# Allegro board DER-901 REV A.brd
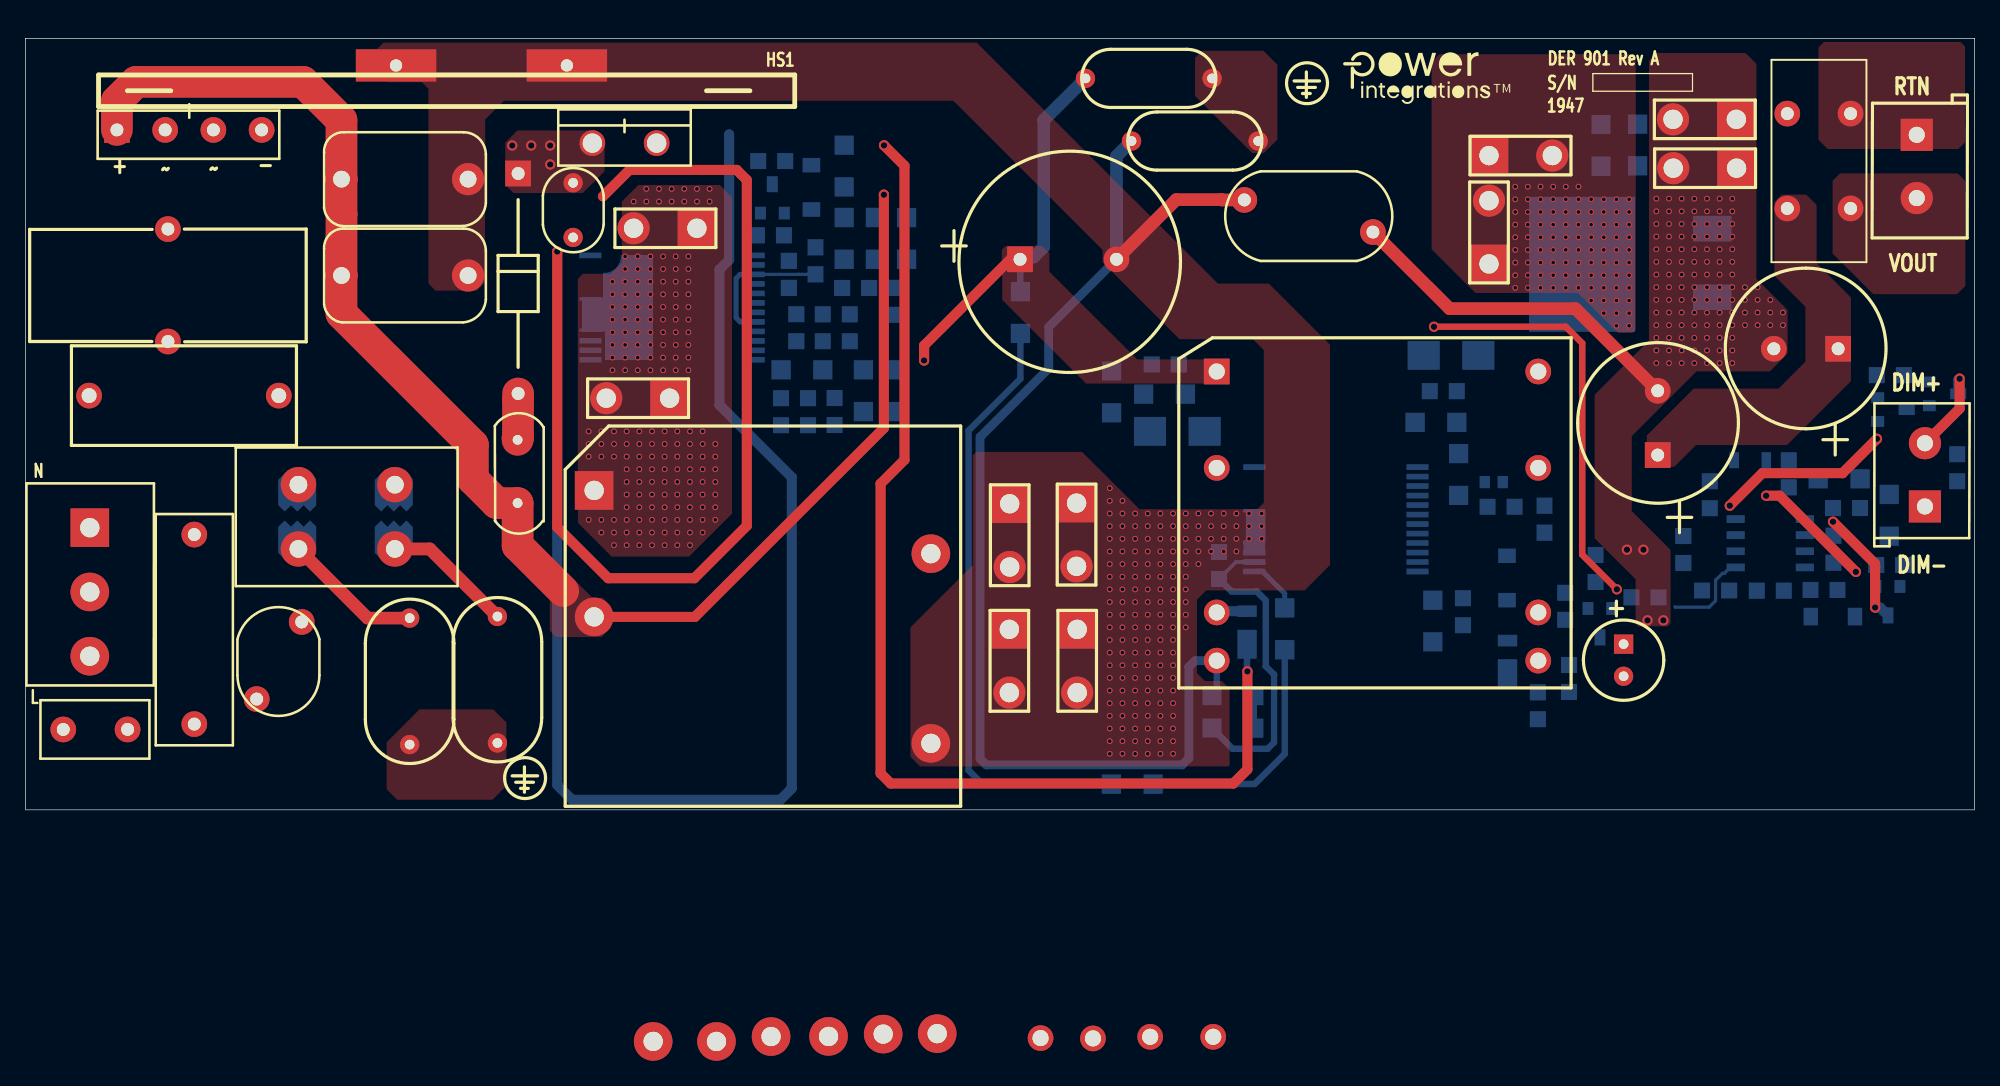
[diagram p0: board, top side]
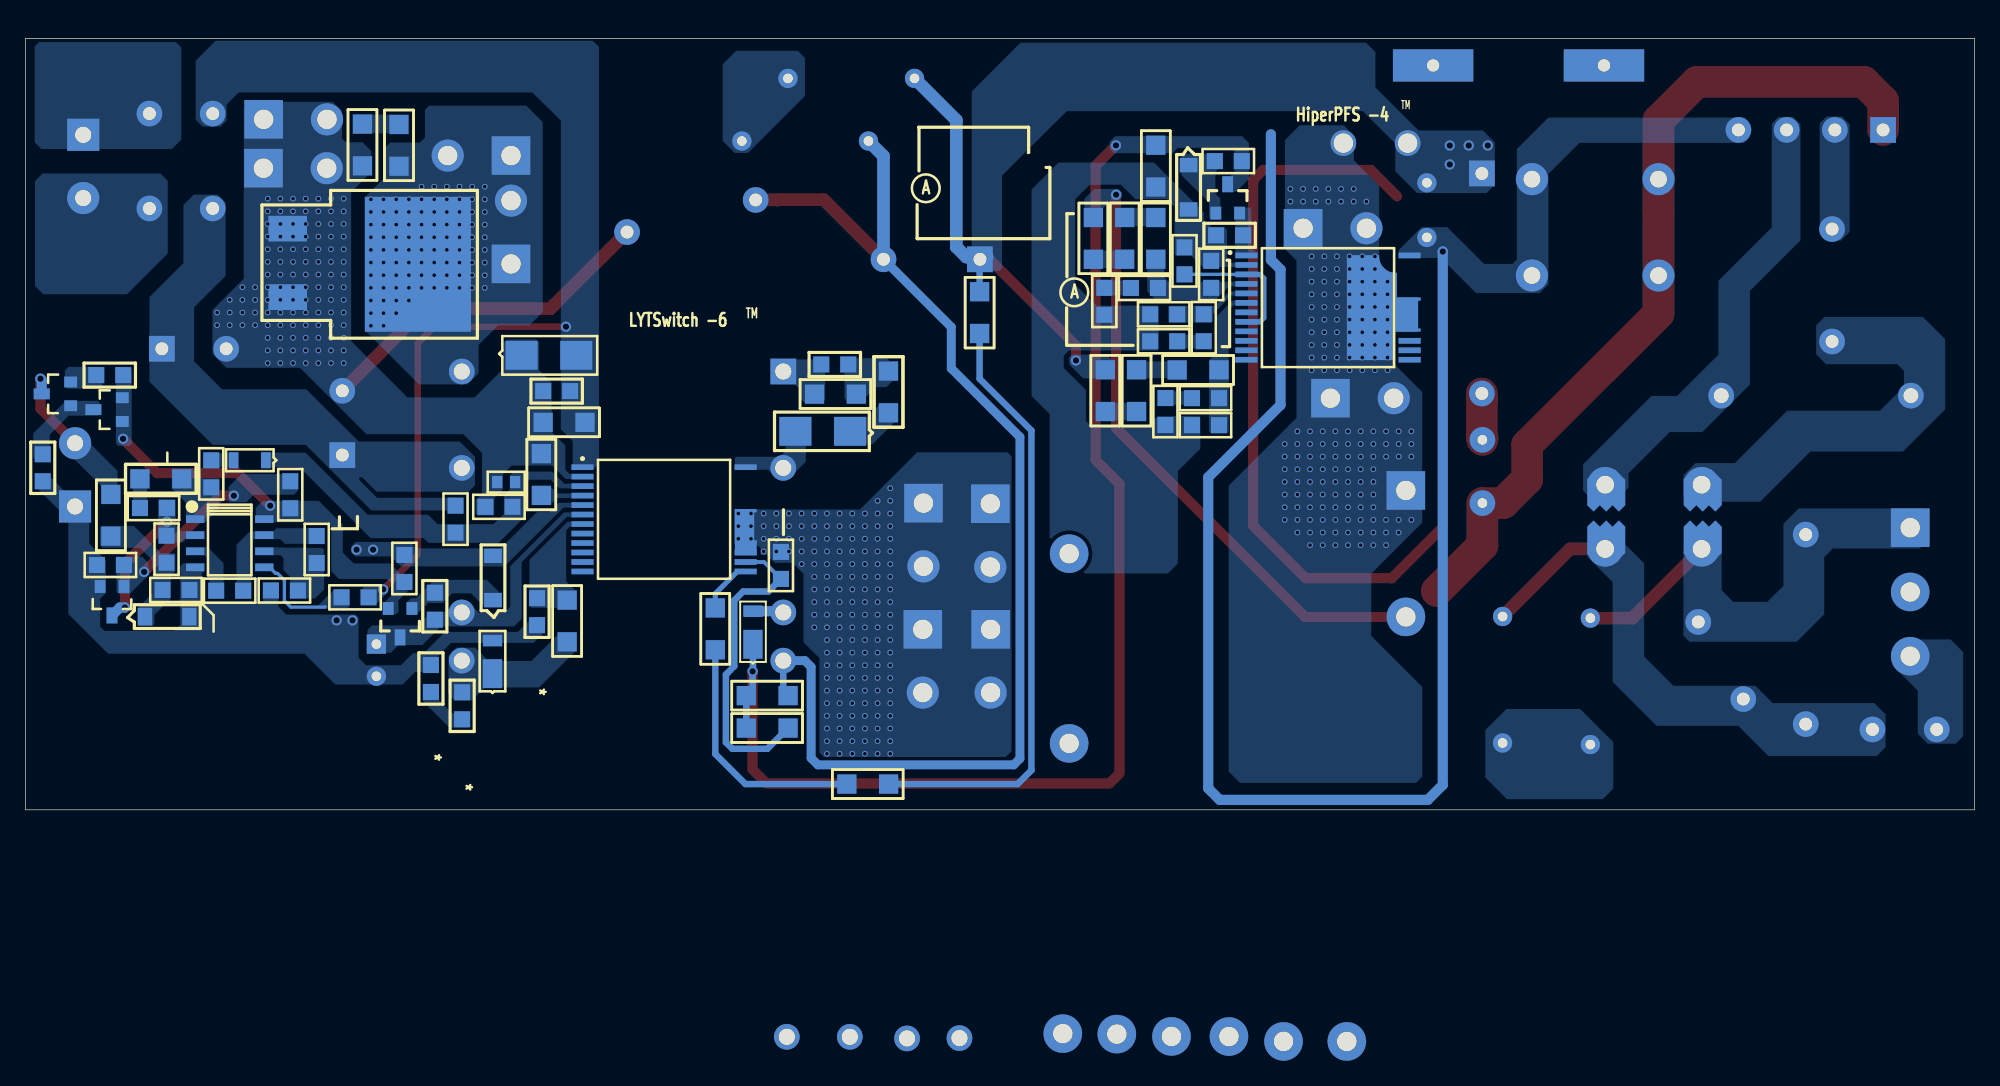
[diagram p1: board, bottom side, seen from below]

Outline 154 x 61 mm; copper layers: TOP, BOTTOM. Coordinates in mm from the lower left corner of the outline.
Outline path: 0,61 0,0 154,0 154,61 0,61

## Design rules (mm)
constraint set DEFAULT: min track width 0.508

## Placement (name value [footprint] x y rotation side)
BR1  UD4KB100-BP  [PIDAXBRIDGED3K]  7.24 53.76 0 top
C1  330 nF  [PI_NP_CAPRAD512X299LS394D040]  24.98 49.87 0 top
C2  330 nF  [PI_NP_CAPRAD512X299LS394D040]  24.98 42.25 0 top
C3  150 nF  [PINPXCAPRAD720X240590040]  13.35 6.78 90 top
C4  330 nF  [PINPXCAPRAD710X315590046]  20.02 32.75 180 top
C7  680 uF  [PIPOLCAPCLYD500LS200040]  128.96 28.05 90 top
C8  680 uF  [PIPOLCAPCLYD500LS200040]  143.21 36.45 180 top
C9  1 nF  [PISMC0805]  88.99 35.22 0 bottom
C10  47 pF  [PISMC1206]  127.37 54.22 270 bottom
C12  3.3 nF  [PINPYCAPRAD540X290LS400040]  96.3 48.22 0 top
C13  68 uF  [PIPOLCAPCLYD710LS300040]  78.58 43.53 0 top
C14  10 nF  [PI_NP_CAP250X200LS170D030]  43.28 49.58 270 top
C15  330 pF  [PISMC0603]  116.72 25.91 180 bottom
C16  2.2 uF  [PISMC1206]  113.23 28.16 270 bottom
C17  1 uF  [PISMC0805]  62.42 42.34 90 bottom
C18  1 uF  [PISMC0805]  57.8 45.43 0 bottom
C19  470 pF  [PISMC0805]  59.7 30.42 0 bottom
C20  10 uF  [PISMC1206]  64.69 52.55 270 bottom
C21  470 pF  [PISMC0805]  60.32 41.27 90 bottom
C22  100 nF  [PISMC0805]  63 39.18 0 bottom
C23  1 uF  [PISMC0805]  63 37.05 0 bottom
C25  1 uF  [PISMC0805]  133.07 25.98 270 bottom
C26  10 uF  [PISMC1206]  97.04 9.03 180 bottom
C27  4.7 uF  [PISMC0805]  94.3 18.26 90 bottom
C28  470 nF  [PISMC1206]  144.94 26.17 180 bottom
C29  3.3 uF  [PISMC0805]  141.03 17.38 0 bottom
C31  47 uF  [PIPOLCAPCYLD250LS100030]  126.26 13.1 270 top
C32  100 nF  [PISMC0805]  124.05 18.02 90 bottom
C33  2200 pF  [PINPCAPRAD9P0D10P0LS030]  37.3 15.29 270 top
C34  2200 pF  [PINPCAPRAD9P0D10P0LS030]  30.36 15.16 270 top
C35  2200 pF  [PINPCAPRAD9P0D10P0LS030]  83.75 57.83 0 top
C36  2200 pF  [PINPCAPRAD9P0D10P0LS030]  97.39 52.88 180 top
C37  22 pF  [PISMC0805]  121.95 11.45 270 bottom
C38  100 pF  [PISMC0805]  113.57 14.6 90 bottom
D2  1N4006  [PIDV200X110X040DO41]  38.93 48.71 270 top
D3  S1K-E3/61T  [PISMDO214AC12]  88.85 29.93 0 bottom
D4  STTH2003CG-TR  [PISMDD2PAK]  133.27 45.96 270 bottom
D5  LQA03TC600  [PIDVT0220ACREVA]  49.88 52.72 180 top
D7  DFLR1400-7  [PISMDDFLR120012]  96.51 13.06 270 bottom
D9  B340A-13-F  [PISMDO214AC12]  114.79 35.94 180 bottom
D11  DFLU1200-7  [PISMDDFLR120012]  117.09 10.74 270 bottom
D13  BAS21HT1G  [PISMSOD323]  135 27.64 0 bottom
F1  3.15 A  [PI_RST_MICROFUSE]  3 6.36 0 top
HS1  HEATSINK, SHTM, DER801, PI CUST, AL 3003  [PI_HS_2P_DER801]  60.78 58.11 90 top
J1  TERMINAL BLOCK  [PI_TERM_BLOCK_3PIN]  5.09 22.31 180 top
J2  TERMINAL BLOCK  [PI_TERM_BLOCK_2PIN_LS200]  149.42 53.37 180 top
J4  TERMINAL BLOCK  [PI_TERM_BLOCK_2PIN_LS200]  150.07 23.99 0 top
J6  CON2  [PI_CONN_QC_TAB_2PIN_LS200]  135.17 54.59 90 top
J7  CON2  [PI_CONN_QC_TAB_2PIN_LS200]  135.19 50.73 90 top
J8  CON2  [PI_CONN_QC_TAB_2PIN_LS200]  115.63 51.73 270 top
J9  CON2  [PI_CONN_QC_TAB_2PIN_LS200]  115.63 43.16 0 top
J10  CON2  [PI_CONN_QC_TAB_2PIN_LS200]  77.74 14.27 180 top
J11  CON2  [PI_CONN_QC_TAB_2PIN_LS200]  77.77 24.2 180 top
J12  CON2  [PI_CONN_QC_TAB_2PIN_LS200]  83.1 14.27 180 top
J13  CON2  [PI_CONN_QC_TAB_2PIN_LS200]  83.05 24.25 180 top
J14  CON2  [PI_CONN_QC_TAB_2PIN_LS200]  50.9 32.55 90 top
J15  CON2  [PI_CONN_QC_TAB_2PIN_LS200]  53.06 45.98 90 top
L1  20mH  [PI_IND_4P_690X512LS300X200D055]  21.57 20.63 90 top
L2  2120-V-RC  [PI_TOROID_2P_350X860_LS330_D038]  11.27 37.03 90 top
L3  1.8 mH  [PI_COIL_16X8_LS8X7P5]  144.2 47.55 90 top
NOREF  -  []  0 0 0 top
NOREF#2  -  []  154 0 90 top
NOREF#3  -  []  104.12 60.37 0 top
Q1  MMBTA06LT1G  [PISMSOT23123_1]  58.07 47.18 180 bottom
Q3  MMBT3906  [PISMSOT23123_1]  150.42 33.83 90 bottom
Q5  2N7002  [PISMSOT23123_1]  148.09 17.66 0 bottom
Q6  MMBTA06LT1G  [PISMSOT23123_1]  125.33 15.92 0 bottom
R4  510 k  [PISMR0805]  120.01 24.05 270 bottom
R5  240 k  [PISMR1206]  91.65 32.87 180 bottom
R6  20  [PISMR1206]  124.48 54.19 270 bottom
R7  15.4 k  [PISMR0805]  115.52 23.96 0 bottom
R8  3.74 M  [PISMR1206]  68.68 34.79 270 bottom
R9  6.2 M  [PISMR1206]  66.21 31.49 90 bottom
R10  6.2 M  [PISMR1206]  69.62 46.83 270 bottom
R11  6.2 M  [PISMR1206]  67.15 43.53 90 bottom
R12  6.2 M  [PISMR1206]  59.7 34.78 0 bottom
R13  3.74 M  [PISMR1206]  64.69 46.83 270 bottom
R14  18.2 k  [PISMR0805]  146.26 34.37 0 bottom
R15  30.1 k  [PISMR0805]  60.91 39.19 270 bottom
R17  10 k  [PISMR0805]  64.53 41.26 0 bottom
R18  143 k  [PISMR0805]  68.76 41.27 270 bottom
R19  10 k  [PISMR0805]  59.7 32.55 0 bottom
R20  143 k  [PISMR0805]  63.93 32.56 270 bottom
R21  15.0 k  [PISMR1206]  97.04 6.47 180 bottom
R22  200 k  [PISMR0805]  139.31 27.63 270 bottom
R23  20.0 k  [PISMR1206]  147.24 21.64 90 bottom
R24  0.02  [PISMR0805]  113.09 33.11 180 bottom
R27  10 k  [PISMR0805]  152.62 28.11 270 bottom
R29  10 k  [PISMR0805]  146.21 19.36 0 bottom
R30  47  [PISMR1206]  111.2 13.28 90 bottom
R31  0.027  [PISMR1206]  113.09 30.64 180 bottom
R32  0.0  [PISMR0805]  142.81 23.86 0 bottom
R34  249 k  [PISMR0805]  130.98 21.65 270 bottom
R37  1.00 k  [PISMR0805]  129.02 16.8 180 bottom
R38  1.00 k  [PISMR0805]  132.46 17.34 0 bottom
R39  1.00 k  [PISMR0805]  138.92 17.33 180 bottom
R41  1.00 k  [PISMR0805]  142.84 21.68 270 bottom
R45  1.33 M  [PISMR1206]  78.61 40.97 270 bottom
R46  1.33 M  [PISMR1206]  85.8 2.04 0 bottom
R47  1.33 M  [PISMR1206]  99.49 12.66 90 bottom
R50  100 k  [PISMR0805]  57.9 51.29 0 bottom
R53  30 k  [PISMR0805]  121.65 15.03 90 bottom
R54  20  [PISMR1206]  85.81 31.39 90 bottom
R55  22  [PISMR0805]  119.49 7.16 90 bottom
RT1  2.5  [PI_RAD150X300LS200D030]  38.89 24.25 90 top
RV1  300 Vac  [PIDISC350X225LS240X140040]  18.28 8.76 90 top
T3  PQ26/25  [PIBOBBINPQ262512P]  94.12 34.66 0 top
T4  EQ30  [PI_BOBBIN_EQ30_V_10P]  44.94 25.26 0 top
U2  PFS7628C  [PI_IC_INSOP24B]  51.09 39.71 180 bottom
U3  LM431BIM3/NOPB  [PISMSOT23123]  146.34 32.58 90 bottom
U4  LYT6070C  [PI_IC_INSOP_24D]  109.98 27.1 180 bottom
U5  TSX712IDT  [PISMSO8]  140.58 22.99 270 bottom
VR1  MMSZ4700T1G  [PI_SM_SOD-123_12]  62.1 50.97 270 bottom
VR2  MMSZ5242B-7-F  [PI_SM_SOD-123_12]  144.55 15.28 180 bottom
VR3  MMSZ4700T1G  [PI_SM_SOD-123_12]  117.05 16.58 90 bottom

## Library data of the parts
BR1 = DISCRETE BRIDGE_+~~-: alternate symbols: (pidaxbridgeD3K_horz)
C1 C2 = CAP NP: alternate symbols: (pi_np_caprad512x299ls394d040_h)
C3 C4 C9 C10 C14-C19 C21-C23 C25 C27-C29 C32-C38 = CAP NP
C7 C8 = CAP POL: alternate symbols: (pipolcapclyd500ls2000401000lh)
C12 = CAP NP: alternate symbols: (pinpycaprad540x290ls400040h)
C13 = CAP POL: alternate symbols: (pi_cap_cly_d710_ls300_040_1000h)
C20 C26 = CAP NP: alternate symbols: (pismc1206_1)
C31 = CAP POL: alternate symbols: (pipolcapcyld250ls100030h)
D2 = DIODE: alternate symbols: (pidax475x125040do41,pidv200x110x040do41wbead,pidax390x125040do41)
D3 D5 D7 D11 = DIODE
D4 = D_DUAL_CK_AKA
D9 = DIODE SCHOTTKY
D13 = DIODE: alternate symbols: (pismsod323_1)
F1 = FUSE: alternate symbols: (pirstmicrofusehoz)
HS1 = hs_2P_DER801
J1 = CON3
J2 J4 J6-J15 = CON2
L1 = INDUCTOR_4P_revD: alternate symbols: (pi_4p_700x400d055_horiz)
L2 = INDUCTOR: alternate symbols: (pi_2p_700x400d055_horiz)
L3 = TORRID 4P_14_23
Q1 Q6 = NPN_BEC
Q3 = PNP_BEC
Q5 = FET_N_GSD
R4-R15 R17-R24 R27 R29-R31 R34 R37-R39 R41 R45-R47 R50 R53-R55 = R
R32 = R: alternate symbols: (pismr0805_1)
RT1 = THERMISTOR: alternate symbols: (pirad400x300ls200040_h)
RV1 = VARISTOR
T3 = BPQ26/25_12P/GENERIC
T4 = BEQ30_10P/GENERIC
U2 = HIPERPFS-4-inSOP24B_0
U3 = TL431/SOT-23_CAR
U4 = LYT6
U5 = TSX712IDT
VR1-VR3 = DIODE_ZENER

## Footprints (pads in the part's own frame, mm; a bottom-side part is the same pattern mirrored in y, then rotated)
PI_BOBBIN_EQ30_V_10P
  rect 3.048x3.048 hole 1.524: 1(0,0)
  round 3.048 hole 1.524: 2(27.102,-42.949) 3(0,-10) 4(18.517,-43.17) 5(22.835,-42.987) 6(26.601,-20) 7(9.665,-43.566) 8(4.663,-43.566) 9(26.601,-5.001) 10(13.978,-43.18)
PI_COIL_16X8_LS8X7P5
  round 2.032 hole 1.016: 1(0,5) 2(7.5,5) 3(7.5,0) 4(0,0)
PI_CONN_QC_TAB_2PIN_LS200
  rect 3.048x3.048 hole 1.524: 1(0,0)
  round 2.54 hole 1.524: 2(0,5.001)
PI_HS_2P_DER801
  rect 2.54x6.35 hole 0.965: 1(0.75,18) 2(0.75,31.5)
PI_IC_INSOP24B
  rect 1.75x0.45 smd: 1(-6.445,4.125) 2(-6.445,3.375) 3(-6.445,2.625) 4(-6.445,1.875) 5(-6.445,1.125) 6(-6.445,0.375) 7(-6.445,-0.375) 8(-6.445,-1.125) 9(-6.445,-1.875) 10(-6.445,-2.625) 11(-6.445,-3.375) 12(-6.445,-4.125) 13(6.445,-4.125) 14(6.445,-3.375) 15(6.445,-2.625) 24(6.445,4.125)
  custom 0.438x0.438 smd: 16(6.445,-0.545)
PI_IC_INSOP_24D
  rect 1.75x0.45 smd: 1(0,0) 2(0,-0.75) 3(0,-1.5) 4(0,-2.25) 5(0,-3) 6(0,-3.75) 7(0,-4.5) 8(0,-5.25) 9(0,-6) 10(0,-6.75) 11(0,-7.5) 12(0,-8.25) 13(12.89,-8.25) 14(12.89,-7.5) 15(12.89,-6.75) 24(12.89,0)
  custom 0.438x0.438 smd: 16(12.89,-4.67)
PI_IND_4P_690X512LS300X200D055
  round 2.794 hole 1.397: 1(0,0) 2(5.08,0) 3(5.08,-7.62) 4(0,-7.62)
PI_NP_CAP250X200LS170D030
  round 1.524 hole 0.762: 1(0,0) 2(4.318,0)
PI_NP_CAPRAD512X299LS394D040
  round 2.54 hole 1.321: 1(0,0) 2(10,0)
PI_RAD150X300LS200D030
  round 2.032 hole 0.762: 1(0,0) 2(5,0)
PI_RST_MICROFUSE
  round 2.032 hole 1.016: 1(0,0) 2(5.08,0)
PI_SM_SOD-123_12
  rect 1.143x1.397 smd: 1(0,0) 2(3.505,0)
PI_TERM_BLOCK_2PIN_LS200
  rect 2.54x2.54 hole 1.27: 1(0,0)
  round 2.54 hole 1.27: 2(0,5.001)
PI_TERM_BLOCK_3PIN
  rect 3.048x3.048 hole 1.524: 1(0,0)
  round 3.048 hole 1.524: 2(0,5.08) 3(0,10.16)
PI_TOROID_2P_350X860_LS330_D038
  round 2.032 hole 1.016: 1(0,0) 2(8.89,0)
PIBOBBINPQ262512P
  rect 2.032x2.032 hole 1.27: 1(0,0)
  round 2.032 hole 1.27: 2(-13.919,-52.705) 3(0,-7.62) 4(-9.779,-52.73) 5(0,-19.05) 6(0,-22.86) 7(25.4,-22.86) 8(25.4,-19.05) 9(-5.258,-52.603) 10(25.4,-7.62) 11(-0.279,-52.603) 12(25.4,0)
PIDAXBRIDGED3K
  rect 2.032x2.032 hole 1.016: 1(0,0)
  round 2.032 hole 1.016: 2(3.81,0) 3(7.62,0) 4(11.43,0)
PIDISC350X225LS240X140040
  round 2.032 hole 1.016: 1(0,0) 2(6.096,-3.556)
PIDV200X110X040DO41
  rect 2.032x2.032 hole 1.016: 1(-1.6,0)
  round 2.032 hole 1.016: 2(15.795,0)
PIDVT0220ACREVA
  round 2.032 hole 1.524: 1(5.08,0) 2(0,0)
PINPCAPRAD9P0D10P0LS030
  round 1.524 hole 0.762: 1(0,0) 2(10,0)
PINPXCAPRAD710X315590046
  round 2.032 hole 1.168: 1(0,0) 2(14.986,0)
PINPXCAPRAD720X240590040
  round 2.032 hole 1.016: 1(0,0) 2(14.986,0)
PINPYCAPRAD540X290LS400040
  round 2.032 hole 1.016: 1(0,0) 2(10.16,-2.54)
PIPOLCAPCLYD500LS200040
  rect 2.032x2.032 hole 1.016: 1(0,0)
  round 2.032 hole 1.016: 2(5.08,0)
PIPOLCAPCLYD710LS300040
  rect 2.032x2.032 hole 1.016: 1(0,0)
  round 2.032 hole 1.016: 2(7.62,0)
PIPOLCAPCYLD250LS100030
  rect 1.524x1.524 hole 0.762: 1(0,0)
  round 1.524 hole 0.762: 2(2.54,0)
PISMC0603
  rect 0.813x0.965 smd: 1(0,0) 2(1.422,0)
PISMC0805
  rect 1.27x1.27 smd: 1(0,0) 2(2.134,0)
PISMC1206
  rect 1.524x1.524 smd: 1(0,0) 2(3.302,0)
PISMDD2PAK
  rect 2.032x3.048 smd: 1(0.005,0) 3(5.42,0)
  rect 10.668x8.382 smd: 2(2.825,10.287)
PISMDDFLR120012
  rect 2.286x1.524 smd: 1(-0.025,0)
  rect 0.914x1.524 smd: 2(-2.642,0)
PISMDO214AC12
  rect 2.54x2.286 smd: 1(0,0) 2(4.318,0)
PISMR0805
  rect 1.27x1.27 smd: 1(0,0) 2(2.134,0)
PISMR1206
  rect 1.524x1.524 smd: 1(0,0) 2(3.302,0)
PISMSO8
  rect 0.61x1.448 smd: 1(0,0) 2(1.27,0) 3(2.54,0) 4(3.81,0) 5(3.81,5.461) 6(2.54,5.461) 7(1.27,5.461) 8(0,5.461)
PISMSOD323
  rect 0.762x1.27 smd: 1(0,0) 2(2.54,0)
PISMSOT23123
  rect 0.864x1.016 smd: 1(-1.88,0) 3(0,0)
  rect 0.864x1.27 smd: 2(-0.94,2.286)
PISMSOT23123_1
  rect 0.864x1.016 smd: 1(-1.88,0) 2(0,0)
  rect 0.864x1.27 smd: 3(-0.94,2.286)

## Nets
GND_EARTH: C33.2 C34.2 C35.2 C36.1
15 VDC AUX: C20.1 C26.1 D7.1 Q1.3 R21.1 R50.1
DIM+: J4.2 Q3.3 R23.2
DIM-: C7.2 C8.2 C10.2 C12.2 C15.1 C16.1 C29.1 C31.2 C32.2 C37.1 C38.1 D4.1 D4.3 D9.1 D11.2 J4.1 J6.1 J6.2 J7.1 J7.2 Q5.2(S) R7.2 R24.1 R27.2 R29.2 R31.1 R38.2 U4.2 U4.5 U5.4 VR2.2 VR3.2
FB_PIN: C15.2 D13.1 R4.2 R7.1 U4.3
NC8: U4.8
NC9: U4.9
NC10: U4.10
NC11: U4.11
NC12: U4.12
NC15: U4.15
RS+: D9.2 L3.2 R24.2 R31.2 R37.2 U4.1
SB_A: D11.1 R30.1 R55.2 T3.7
SB_B: C31.1 Q6.3 R53.1 T3.8 U4.6
SOURCE: BR1.4 C1.2 C2.2 C12.1 C13.2 C14.2 C26.2 C27.2 C36.2 HS1.1 HS1.2 J10.1 J10.2 J11.1 J11.2 J12.1 J12.2 J13.1 J13.2 T3.6 T4.6 U2.24 U4.16
VRECT: BR1.1 C1.1 C2.1 R10.1 RT1.1 T4.3
N11474046: F1.1 J1.3
N11474062: C3.1 C33.1 F1.2 L1.4 RV1.1
N11474114: BR1.3(AC2) C4.1 L1.3
N11474138: BR1.2 L2.2
N11474236: C3.2 C34.1 J1.1 L1.1 RV1.2
N11474420: C4.2 L1.2 L2.1
N11475153: C9.2 C13.1 C14.1 C35.1 D2.1 D5.1 R5.1 R8.1 R45.1 T3.1
N11476179: D5.2 J14.1 J14.2 J15.1 J15.2 T4.1 U2.16
N11479125: C18.1 Q1.2(EMITTER) U2.1(VCC)
N11479237: C17.2 C18.2 C19.2 C20.2 C21.2 C22.2 C23.2 R18.2 R20.2 U2.2 U2.12 VR1.2
N11479555: C22.1 R15.1 U2.5
N11479611: C23.1 R15.2
N11480020: C21.1 R13.2 R17.1 U2.4
N11480864: R10.2 R11.1
N11480868: R11.2 R13.1
N11482311: R8.2 R9.1
N11482333: R9.2 R12.2
N11482355: C19.1 R12.1 R19.1 U2.6
N11498787: C7.1 C8.1 L3.1 R4.1 T3.10
N11498945: C9.1 R5.2 R54.2
N11499171: D4.2(CATHODE) J8.1 J8.2 J9.1 J9.2 R6.2 T3.12
N11499175: C10.1 R6.1
N11499225: D3.2 T3.3 U4.24
N11499609: C38.2 R30.2 U4.7
N11499655: C16.2 U4.4
N11499799: C27.1 R21.2 U4.14
N11939314: R19.2 R20.1
N11966145: D7.2 T3.5
N11977822: C17.1 U2.3 U2.8
N11995900: Q1.1 R50.2 VR1.1
N12000412: R17.2 R18.1
N12016680: R45.2 R46.1
N12017060: R46.2 R47.1
N12033400: C25.2 C32.1 Q6.2(EMITTER) R14.1 U3.1 U3.3(VREF) U5.8
N12033444: Q3.2(EMITTER) R14.2
N12033508: Q3.1 R27.1 U3.2
N12033698: R39.1 U5.3
N12033710: C29.2 R23.1 R41.2 VR2.1
N12033758: D13.2 R22.1
N12033766: C28.2 R22.2 U5.1
N12033774: Q5.3 R32.1 R41.1 U5.2
N12033856: C25.1 Q5.1 R29.1
N12033928: C28.1 R32.2
N12034132: R34.2 R38.1 U5.6
N12034136: R34.1 R39.2 U5.7(OUT)
N12052159: Q6.1 R53.2 VR3.1
N12053445: D3.1 R54.1
N12080403: R37.1 U5.5
N12174734: C37.2 R55.1
N12244813: D2.2 RT1.2
N12258356: R47.2 U4.13(VPIN)
N12288102: J2.2 L3.4
N12288115: J2.1 L3.3

Pads without a net: J1 2; T3 2 4 9 11; T4 2 4 5 7 8 9 10; U2 7 9 10 11 13 14 15

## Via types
v1: diameter 0.457, hole 0.305, TOP to BOTTOM, 534 vias
v2: diameter 0.813, hole 0.508, TOP to BOTTOM, 22 vias

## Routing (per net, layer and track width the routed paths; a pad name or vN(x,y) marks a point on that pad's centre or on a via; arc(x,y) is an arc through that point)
15 VDC AUX: length 95.5
  TOP w0.8: v2(96.55,10.95) 96.55,3.2 95.43,2.08 68.36,2.08 67.56,2.88 67.56,25.78 69.45,27.67 69.45,50.92 v2(67.84,52.54)
  BOTTOM w0.508: R21.1 97.04,7.74 C26.1 96.55,9.53 v2(96.55,10.95) 96.51,10.98 D7.1
DIM+: length 7.5
  TOP w0.8: J4.2 152.81,31.72 v2(152.81,34.09)
  BOTTOM w0.8: v2(152.81,34.09) 152.7,33.98 Q3.3
DIM-: length 27.7
  TOP w1: C12.2 112.52,39.62 122.47,39.62 C7.2
  vias: v1(128.85,48.32) v1(128.85,47.32) v1(128.85,46.32) v1(128.85,45.32) v1(128.85,44.32) v1(128.85,43.32) v1(128.85,42.32) v1(128.85,41.32) v1(128.85,40.32) v1(128.85,39.32) v1(128.85,38.32) v1(128.85,37.32) v1(128.85,36.32) v1(128.85,35.32) v1(129.85,48.32) v1(129.85,47.32) v1(129.85,46.32) v1(129.85,45.32) v1(129.85,44.32) v1(129.85,43.32) v1(129.85,42.32) v1(129.85,41.32) v1(129.85,40.32) v1(129.85,39.32) v1(129.85,38.32) v1(129.85,37.32) v1(129.85,36.32) v1(129.85,35.32) v1(130.85,48.32) v1(130.85,47.32) v1(130.85,46.32) v1(130.85,45.32) v1(130.85,44.32) v1(130.85,43.32) v1(130.85,42.32) v1(130.85,41.32) v1(130.85,40.32) v1(130.85,39.32) v1(130.85,38.32) v1(130.85,37.32) v1(130.85,36.32) v1(130.85,35.32) v1(131.85,48.32) v1(131.85,47.32) v1(131.85,46.32) v1(131.85,45.32) v1(131.85,44.32) v1(131.85,43.32) v1(131.85,42.32) v1(131.85,41.32) v1(131.85,40.32) v1(131.85,39.32) v1(131.85,38.32) v1(131.85,37.32) v1(131.85,36.32) v1(131.85,35.32) v1(132.85,48.32) v1(132.85,47.32) v1(132.85,46.32) v1(132.85,45.32) v1(132.85,44.32) v1(132.85,43.32) v1(132.85,42.32) v1(132.85,41.32) v1(132.85,40.32) v1(132.85,39.32) v1(132.85,38.32) v1(132.85,37.32) v1(132.85,36.32) v1(132.85,35.32) v1(133.85,48.32) v1(133.85,47.32) v1(133.85,46.32) v1(133.85,45.32) v1(133.85,44.32) v1(133.85,43.32) v1(133.85,42.32) v1(133.85,41.32) v1(133.85,40.32) v1(133.85,39.32) v1(133.85,38.32) v1(133.85,37.32) v1(133.85,36.32) v1(133.85,35.32) v1(134.85,48.32) v1(134.85,47.32) v1(134.85,46.32) v1(134.85,45.32) v1(134.85,44.32) v1(134.85,43.32) v1(134.85,42.32) v1(134.85,41.32) v1(134.85,40.32) v1(134.85,39.32) v1(134.85,38.32) v1(134.85,37.32) v1(134.85,36.32) v1(134.85,35.32) v1(135.85,41.32) v1(135.85,40.32) v1(135.85,39.32) v1(135.85,38.32) v1(136.85,41.32) v1(136.85,40.32) v1(136.85,39.32) v1(136.85,38.32) v1(137.85,40.32) v1(137.85,39.32) v1(137.85,38.32) v1(138.85,39.32) v1(138.85,38.32) v2(126.53,20.57) v2(127.83,20.57) v2(128.15,14.98) v2(129.41,14.98)
RS+: length 32.8
  TOP w0.508: v2(111.29,38.2) 121.7,38.2 123,36.9 123,20.17 v2(125.73,17.44)
SOURCE: length 291.3
  TOP w0.8: 45.63,48.5 47.73,50.6 56.2,50.6 57,49.8 57,22.46 52.85,18.31 46.05,18.31 42.02,22.34 v2(42.02,44.14)
  TOP w1: C12.1 94.53,48.22 94.51,48.25 90.92,48.25 C13.2
  BOTTOM w0.508: T3.6 94.12,9.41 C26.2
  BOTTOM w0.7: T3.6 92.42,11.8 91.92,11.3 91.92,4.09 91.39,3.56 75.92,3.56 75.43,4.05 75.43,29.48 80.85,34.9 80.85,38.17 C13.2
  BOTTOM w0.8: v2(42.02,44.14) 42.02,1.97 43.21,0.79 59.64,0.79 60.55,1.7 60.55,26.3 54.84,32.01 54.84,42.72 55.6,43.48 55.6,53.42
  BOTTOM w1: C13.2 86.2,51.69 C36.2
  vias: v1(85.67,25.43) v1(85.67,24.43) v1(85.67,23.43) v1(85.67,22.43) v1(85.67,21.43) v1(85.67,20.43) v1(85.67,19.43) v1(85.67,18.43) v1(85.67,17.43) v1(85.67,16.43) v1(85.67,15.43) v1(85.67,14.43) v1(85.67,13.43) v1(85.67,12.43) v1(85.67,11.43) v1(85.67,10.43) v1(85.67,9.43) v1(85.67,8.43) v1(85.67,7.43) v1(85.67,6.43) v1(85.67,5.43) v1(85.67,4.43) v1(86.67,24.43) v1(86.67,23.43) v1(86.67,22.43) v1(86.67,21.43) v1(86.67,20.43) v1(86.67,19.43) v1(86.67,18.43) v1(86.67,17.43) v1(86.67,16.43) v1(86.67,15.43) v1(86.67,14.43) v1(86.67,13.43) v1(86.67,12.43) v1(86.67,11.43) v1(86.67,10.43) v1(86.67,9.43) v1(86.67,8.43) v1(86.67,7.43) v1(86.67,6.43) v1(86.67,5.43) v1(86.67,4.43) v1(87.67,23.43) v1(87.67,22.43) v1(87.67,21.43) v1(87.67,20.43) v1(87.67,19.43) v1(87.67,18.43) v1(87.67,17.43) v1(87.67,16.43) v1(87.67,15.43) v1(87.67,14.43) v1(87.67,13.43) v1(87.67,12.43) v1(87.67,11.43) v1(87.67,10.43) v1(87.67,9.43) v1(87.67,8.43) v1(87.67,7.43) v1(87.67,6.43) v1(87.67,5.43) v1(87.67,4.43) v1(88.67,23.43) v1(88.67,22.43) v1(88.67,21.43) v1(88.67,20.43) v1(88.67,19.43) v1(88.67,18.43) v1(88.67,17.43) v1(88.67,16.43) v1(88.67,15.43) v1(88.67,14.43) v1(88.67,13.43) v1(88.67,12.43) v1(88.67,11.43) v1(88.67,10.43) v1(88.67,9.43) v1(88.67,8.43) v1(88.67,7.43) v1(88.67,6.43) v1(88.67,5.43) v1(88.67,4.43) v1(89.67,23.43) v1(89.67,22.43) v1(89.67,21.43) v1(89.67,20.43) v1(89.67,19.43) v1(89.67,18.43) v1(89.67,17.43) v1(89.67,16.43) v1(89.67,15.43) v1(89.67,14.43) v1(89.67,13.43) v1(89.67,12.43) v1(89.67,11.43) v1(89.67,10.43) v1(89.67,9.43) v1(89.67,8.43) v1(89.67,7.43) v1(89.67,6.43) v1(89.67,5.43) v1(89.67,4.43) v1(90.67,23.43) v1(90.67,22.43) v1(90.67,21.43) v1(90.67,20.43) v1(90.67,19.43) v1(90.67,18.43) v1(90.67,17.43) v1(90.67,16.43) v1(90.67,15.43) v1(90.67,14.43) v1(90.67,13.43) v1(90.67,12.43) v1(90.67,11.43) v1(90.67,10.43) v1(90.67,9.43) v1(90.67,8.43) v1(90.67,7.43) v1(90.67,6.43) v1(90.67,5.43) v1(90.67,4.43) v1(91.67,23.43) v1(91.67,22.43) v1(91.67,21.43) v1(91.67,20.43) v1(91.67,19.43) v1(91.67,18.43) v1(91.67,17.43) v1(91.67,16.43) v1(91.67,15.43) v1(91.67,14.43) v1(92.67,23.43) v1(92.67,22.43) v1(92.67,21.43) v1(92.67,20.43) v1(92.67,19.43) v1(93.67,23.43) v1(93.67,22.43) v1(93.67,21.43) v1(93.67,20.43) v1(94.67,23.43) v1(94.67,22.43) v1(94.67,21.43) v1(94.67,20.43) v1(95.67,23.43) v1(95.67,22.43) v1(95.67,21.43) v1(95.67,20.43) v1(96.67,23.43) v1(96.67,22.43) v1(96.67,21.43) v1(97.67,23.43) v1(97.67,22.43) v1(97.67,21.43)
VRECT: length 114.9
  TOP w0.8: T4.3 52.9,15.26 67.83,30.18 v2(67.83,48.64)
  TOP w2.5: 42.49,17.3 38.89,20.9 RT1.1 37.24,24.25 35.36,26.14 35.36,28.85 24.98,39.23 C2.1 24.98,47.09 C1.1 24.98,54.52 21.95,57.56 8.75,57.56 7.24,56.04 BR1.1
N11474062: length 10.3
  TOP w1: L1.4 31.96,20.63 C33.1
N11474236: length 11.1
  TOP w1: L1.1 27.04,15.16 C34.1
N11475153: length 31.1
  TOP w0.8: 78,43.71 71,36.71 v2(71,35.53)
  BOTTOM w0.508: R45.1 78.61,43.5 C13.1
  BOTTOM w1: C35.1 80.45,54.53 80.45,44.5 79.66,43.71 78,43.71
  vias: v2(38.47,52.53) v2(39.97,52.53) v2(41.47,52.53) v2(41.47,51.03)
N11476179:
  vias: v1(44.51,29.93) v1(44.51,28.93) v1(44.51,27.93) v1(44.51,22.93) v1(45.51,29.93) v1(45.51,28.93) v1(45.51,27.93) v1(45.51,22.93) v1(45.51,21.93) v1(46.38,41.76) v1(46.38,40.76) v1(46.38,39.76) v1(46.38,38.76) v1(46.38,37.76) v1(46.38,36.76) v1(46.38,35.76) v1(46.38,34.76) v1(46.51,29.93) v1(46.51,28.93) v1(46.51,27.93) v1(46.51,22.93) v1(46.51,21.93) v1(46.51,20.93) v1(47.38,43.76) v1(47.38,42.76) v1(47.38,41.76) v1(47.38,40.76) v1(47.38,39.76) v1(47.38,38.76) v1(47.38,37.76) v1(47.38,36.76) v1(47.38,35.76) v1(47.38,34.76) v1(47.51,29.93) v1(47.51,28.93) v1(47.51,27.93) v1(47.51,26.93) v1(47.51,25.93) v1(47.51,24.93) v1(47.51,23.93) v1(47.51,22.93) v1(47.51,21.93) v1(47.51,20.93) v1(48.06,48.09) v1(48.38,43.76) v1(48.38,42.76) v1(48.38,41.76) v1(48.38,40.76) v1(48.38,39.76) v1(48.38,38.76) v1(48.38,37.76) v1(48.38,36.76) v1(48.38,35.76) v1(48.38,34.76) v1(48.51,29.93) v1(48.51,28.93) v1(48.51,27.93) v1(48.51,26.93) v1(48.51,25.93) v1(48.51,24.93) v1(48.51,23.93) v1(48.51,22.93) v1(48.51,21.93) v1(48.51,20.93) v1(49.06,49.09) v1(49.06,48.09) v1(49.38,43.76) v1(49.38,42.76) v1(49.38,41.76) v1(49.38,40.76) v1(49.38,39.76) v1(49.38,38.76) v1(49.38,37.76) v1(49.38,36.76) v1(49.38,35.76) v1(49.38,34.76) v1(49.51,29.93) v1(49.51,28.93) v1(49.51,27.93) v1(49.51,26.93) v1(49.51,25.93) v1(49.51,24.93) v1(49.51,23.93) v1(49.51,22.93) v1(49.51,21.93) v1(49.51,20.93) v1(50.06,49.09) v1(50.06,48.09) v1(50.38,43.76) v1(50.38,42.76) v1(50.38,41.76) v1(50.38,40.76) v1(50.38,39.76) v1(50.38,38.76) v1(50.38,37.76) v1(50.38,36.76) v1(50.38,35.76) v1(50.38,34.76) v1(50.51,29.93) v1(50.51,28.93) v1(50.51,27.93) v1(50.51,26.93) v1(50.51,25.93) v1(50.51,24.93) v1(50.51,23.93) v1(50.51,22.93) v1(50.51,21.93) v1(50.51,20.93) v1(51.06,49.09) v1(51.06,48.09) v1(51.38,43.76) v1(51.38,42.76) v1(51.38,41.76) v1(51.38,40.76) v1(51.38,39.76) v1(51.38,38.76) v1(51.38,37.76) v1(51.38,36.76) v1(51.38,35.76) v1(51.38,34.76) v1(51.51,29.93) v1(51.51,28.93) v1(51.51,27.93) v1(51.51,26.93) v1(51.51,25.93) v1(51.51,24.93) v1(51.51,23.93) v1(51.51,22.93) v1(51.51,21.93) v1(51.51,20.93) v1(52.06,49.09) v1(52.06,48.09) v1(52.38,43.76) v1(52.38,42.76) v1(52.38,41.76) v1(52.38,40.76) v1(52.38,39.76) v1(52.38,38.76) v1(52.38,37.76) v1(52.38,36.76) v1(52.38,35.76) v1(52.38,34.76) v1(52.51,29.93) v1(52.51,28.93) v1(52.51,27.93) v1(52.51,26.93) v1(52.51,25.93) v1(52.51,24.93) v1(52.51,23.93) v1(52.51,22.93) v1(52.51,21.93) v1(52.51,20.93) v1(53.06,49.09) v1(53.06,48.09) v1(53.51,29.93) v1(53.51,28.93) v1(53.51,27.93) v1(53.51,26.93) v1(53.51,25.93) v1(53.51,24.93) v1(53.51,23.93) v1(53.51,22.93) v1(53.51,21.93) v1(54.06,49.09) v1(54.06,48.09) v1(54.51,28.93) v1(54.51,27.93) v1(54.51,26.93) v1(54.51,25.93) v1(54.51,24.93) v1(54.51,23.93) v1(54.51,22.93)
N11499171:
  vias: v1(117.7,49.27) v1(117.7,48.27) v1(117.7,47.27) v1(117.7,46.27) v1(117.7,45.27) v1(117.7,44.27) v1(117.7,43.27) v1(117.7,42.27) v1(117.7,41.27) v1(118.7,49.27) v1(118.7,48.27) v1(118.7,47.27) v1(118.7,46.27) v1(118.7,45.27) v1(118.7,44.27) v1(118.7,43.27) v1(118.7,42.27) v1(118.7,41.27) v1(119.7,49.27) v1(119.7,48.27) v1(119.7,47.27) v1(119.7,46.27) v1(119.7,45.27) v1(119.7,44.27) v1(119.7,43.27) v1(119.7,42.27) v1(119.7,41.27) v1(120.7,49.27) v1(120.7,48.27) v1(120.7,47.27) v1(120.7,46.27) v1(120.7,45.27) v1(120.7,44.27) v1(120.7,43.27) v1(120.7,42.27) v1(120.7,41.27) v1(121.7,49.27) v1(121.7,48.27) v1(121.7,47.27) v1(121.7,46.27) v1(121.7,45.27) v1(121.7,44.27) v1(121.7,43.27) v1(121.7,42.27) v1(121.7,41.27) v1(122.7,49.27) v1(122.7,48.27) v1(122.7,47.27) v1(122.7,46.27) v1(122.7,45.27) v1(122.7,44.27) v1(122.7,43.27) v1(122.7,42.27) v1(122.7,41.27) v1(123.7,48.27) v1(123.7,47.27) v1(123.7,46.27) v1(123.7,45.27) v1(123.7,44.27) v1(123.7,43.27) v1(123.7,42.27) v1(123.7,41.27) v1(123.7,40.27) v1(124.7,48.27) v1(124.7,47.27) v1(124.7,46.27) v1(124.7,45.27) v1(124.7,44.27) v1(124.7,43.27) v1(124.7,42.27) v1(124.7,41.27) v1(124.7,40.27) v1(124.7,39.27) v1(125.7,48.27) v1(125.7,47.27) v1(125.7,46.27) v1(125.7,45.27) v1(125.7,44.27) v1(125.7,43.27) v1(125.7,42.27) v1(125.7,41.27) v1(125.7,40.27) v1(125.7,39.27) v1(125.7,38.27) v1(126.7,48.27) v1(126.7,47.27) v1(126.7,46.27) v1(126.7,45.27) v1(126.7,44.27) v1(126.7,43.27) v1(126.7,42.27) v1(126.7,41.27) v1(126.7,40.27) v1(126.7,39.27) v1(126.7,38.27)
N11499799: length 25
  BOTTOM w0.3: U4.14 95.64,19.6 C27.1
  BOTTOM w0.508: C27.1 95.3,17.26 97.29,17.26 97.99,16.56 97.99,11.35 98.65,10.69 98.65,5.33 98.15,4.83 95.38,4.83 R21.2
N11966145: length 2.4
  BOTTOM w0.8: T3.5 94.22,15.71 D7.2
N11977822: length 11
  BOTTOM w0.254: U2.3 59.5,42.33 59.51,42.34 61.13,42.34 61.14,42.33 61.41,42.33 61.41,42.34 C17.1
  BOTTOM w0.4: U2.8 56.47,38.58 56.15,38.9 56.15,42.02 56.47,42.33 U2.3
N12016680: length 48
  BOTTOM w0.508: R46.1 75.61,2.04 74.52,3.13 74.52,29.99 78.61,34.09 R45.2
N12017060: length 19.6
  BOTTOM w0.508: R46.2 97.11,2.04 99.49,4.42 R47.1
N12033400: length 13.8
  TOP w0.8: v2(134.65,24.05) 137.22,26.62 143.56,26.62 v2(146.28,29.34)
N12033774: length 9.4
  TOP w0.8: v2(142.81,22.78) 146.12,19.47 146.13,19.26 146.14,19.25 v2(146.14,16)
  BOTTOM w0.8: Q5.3 146.53,16 v2(146.14,16)
N12033856: length 9.6
  TOP w0.8: v2(144.61,18.82) 138.59,24.84 v2(137.52,24.84)
N12080403: length 7.1
  BOTTOM w0.254: 130.33,16.05 130.35,16.03 133.03,16.03 133.53,16.53 133.53,18.16 134.07,18.69 134.22,18.69 134.7,19.18 U5.5
N12244813: length 3.7
  TOP w2.5: D2.2 38.93,32.46 38.92,32.45 38.92,29.44 38.89,29.41 RT1.2
N12258356: length 4.3
  BOTTOM w0.4: U4.13 97.74,18.85 99.49,17.1 R47.2

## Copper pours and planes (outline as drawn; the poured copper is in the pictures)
GND_EARTH on TOP: 36.97,7.95 31.14,7.95 28.55,5.36 28.55,1.63 29.38,0.8 36.9,0.8 38.01,1.9 38.01,6.9
GND_EARTH on TOP: 92.97,60.02 92.41,59.46 92.41,56.43 96.91,51.94 97.84,51.94 98.91,53.01 98.91,58.92 97.82,60.02
GND_EARTH on BOTTOM: 36.95,0.85 38.01,1.9 38.01,1.91 38.66,2.56 38.66,6.3 36.99,7.97 31.16,7.97 28.55,5.36 28.55,1.68 29.38,0.85
GND_EARTH on BOTTOM: 96.91,51.94 97.95,51.94 98.91,52.89 98.91,58.95 97.84,60.02 92.97,60.02 92.41,59.46 92.41,56.43
15 VDC AUX on BOTTOM: 57.34,49.88 57.34,52.73 57.87,53.26 67.9,53.26 68.34,52.83 68.34,52.27 67.98,51.91 63.38,51.91 62.95,52.35 58.68,52.35 58.48,52.14 58.48,50.44 59.29,49.63 59.29,48.94 59.22,48.87 58.35,48.87
DIM+ on BOTTOM: 146.71,24.46 146.71,26.8 149.68,29.77 150.52,29.77 150.9,29.39 150.9,28.5 147.9,25.5 147.9,24.43 147.73,24.26 146.91,24.26
DIM- on TOP: 126.91,23.62 129.97,20.55 129.97,14.73 129.74,14.5 127.44,14.5 127.21,14.73 127.21,18.23 123.98,21.47 123.98,30.65 123.98,30.65 123.98,32.82 128.27,37.11 128.27,59.23 128.88,59.84 135.89,59.84 136.75,58.98 136.75,41.99 139.22,39.52 139.22,36.07 137.81,34.66 132.02,34.66 126.91,29.55
DIM- on BOTTOM: 109.79,26.54 110.98,26.54 111.34,26.89 111.34,28.8 112.15,29.61 112.15,29.62 112.42,29.89 112.42,33.77 113.42,34.77 113.42,36.98 113.64,37.19 115.93,37.19 116.27,36.86 116.27,34.84 118.5,32.61 123.81,32.61 128.26,37.06 128.26,48.84 126.67,50.43 126.67,52.1 127.36,52.78 128.68,52.78 128.98,53.09 128.98,55.24 129.72,55.98 136.25,55.98 136.74,55.49 136.74,42 139.22,39.52 139.22,36.04 138.13,34.95 132.3,34.95 127.05,29.7 119.4,29.7 117.92,28.22 117.92,25.02 118.42,24.51 118.42,23.41 118.27,23.26 117.03,23.26 116.95,23.34 116.95,24.66 116.27,25.35 116.27,26.54 115.58,27.22 112.38,27.22 111.31,26.16 109.76,26.16 109.71,26.21 109.71,26.46
DIM- on BOTTOM: 115.09,14.07 113.95,15.21 113,15.21 113,14.05 113.85,13.2 120.35,13.2 121.41,12.15 121.41,10.98 121.5,10.89 123.22,10.89 124.2,9.91 129.5,9.91 131.94,12.34 147.46,12.34 150.61,15.49 150.61,22.97 153.16,25.53 153.16,26.31 153.01,26.47 152.17,26.47 150.9,25.2 149.17,25.2 148.95,24.97 148.95,21.04 147.63,19.73 147.63,17.14 148.09,16.68 148.09,14.5 147.74,14.14 142.25,14.14 141.77,14.63 141.77,19.27 141.56,19.48 139.86,19.48 139.86,18.89 140.06,18.69 140.06,16.51 139.89,16.33 135.33,16.33 135.2,16.46 135.2,17.75 135.08,17.88 134.14,17.88 134.03,17.77 134.03,16.09 133.38,15.44 127.89,15.44 127.68,15.23 127.68,13.2 127.67,13.2 127.67,12.03 127.08,11.43 124.33,11.43 123.37,12.39 122.51,12.39 120.84,14.07
DIM- on BOTTOM: 109.86,24.28 111.85,24.28 112.58,23.54 113.57,23.54 116.44,20.67 123.12,20.67 123.63,21.18 127.9,21.18 128.27,20.81 128.27,20.38 127.92,20.04 125.1,20.04 124.32,19.25 116.14,19.25 111.49,23.9 109.86,23.9 109.76,24 109.76,24.18
FB_PIN on BOTTOM: 109.79,25.78 111.41,25.78 112.38,26.74 115.4,26.74 115.73,26.41 115.73,25.29 116.19,24.84 116.19,23.39 116.62,22.96 116.65,22.96 117.02,22.58 121.43,22.58 122.18,23.34 126.96,23.34 131.86,28.24 135.16,28.24 135.34,28.06 135.34,27.25 135.16,27.07 134.71,27.07 134.69,27.09 132.33,27.09 126.73,21.48 122.52,21.48 122.15,21.11 116.61,21.11 114.59,23.14 114.59,25.73 114.21,26.11 112.51,26.11 111.82,25.42 109.76,25.42 109.71,25.47 109.71,25.7
RS+ on BOTTOM: 110.75,27 110.75,29.16 111.69,30.1 111.69,38.55 111.59,38.65 108.69,38.65 108.69,27.37 109.16,26.89 110.65,26.89
RS+ on BOTTOM: 109.17,60.81 108.69,60.33 108.69,37.51 111.54,37.51 111.69,37.66 111.69,54.49 112.95,55.75 112.98,55.75 113.94,56.72 137.13,56.72 138.1,55.75 138.1,54.51 138.58,54.03 140,54.03 140.54,54.56 140.54,59.23 138.96,60.81
RS+ on BOTTOM: 126.32,16.23 127.06,16.23 127.31,16.48 127.31,17.62 127.19,17.75 125.54,17.75 125.36,17.57 125.36,17.19
SB_A on BOTTOM: 119.92,12.82 120.57,12.17 120.57,9.14 120.09,8.66 118.72,8.66 117.71,9.67 113.41,9.67 110.49,12.6 110.49,13.97 111.81,13.97 114.01,11.77 117.39,11.77 118.45,12.82
SB_B on BOTTOM: 109.84,23.52 111.44,23.52 115.68,19.27 115.68,16.07 116.19,15.57 118.14,15.57 119.1,16.52 119.96,16.52 120.84,15.64 121.93,15.64 122.64,14.93 122.66,14.93 123.01,14.58 126.59,14.58 126.97,14.2 126.97,12.52 126.87,12.42 125.12,12.42 124.51,13.03 122.64,13.03 121.17,14.5 115.39,14.5 114.78,15.11 114.78,19.59 111.21,23.16 109.84,23.16 109.76,23.24 109.76,23.44
SOURCE on BOTTOM (solid shape): 97.94,20.14 96.22,20.14 96.22,21.15 97.94,21.15
SOURCE on TOP: 36.33,49.48 36.31,49.47 36.31,41.69 35.66,41.05 32.41,41.05 31.85,41.61 31.85,57 31.32,57.53 28.65,57.53 27.66,58.52 27.66,60.02 28.3,60.66 75.16,60.66 94.21,41.61 98.24,41.61 103.07,36.78 103.07,19.35 101.07,17.35 93.29,17.35 92.56,16.61 92.56,10.82 93.19,10.19 94.51,10.19 95.14,9.56 95.14,3.54 95.02,3.43 70.69,3.43 69.93,4.19 69.93,14.43 74.85,19.35 74.85,28.04 75.11,28.3 83.49,28.3 88.01,23.77 97.33,23.77 97.84,24.28 97.84,36.35 96.98,37.21 91.19,37.21 85.12,43.28 85.12,44.27 73.32,56.06 37.8,56.06 36.33,54.59
SOURCE on BOTTOM: 33.67,41.55 34.36,40.86 39.4,40.86 42.17,43.63 45.5,43.63 45.5,44.26 43.69,46.07 41.66,46.07 38.75,43.16 36.52,43.16 36.17,43.51 36.17,52.25 33.68,54.74 18.16,54.74 17.83,54.41 17.83,53.11 18.21,52.73 31.22,52.73 33.67,50.27
SOURCE on BOTTOM: 97.92,23.75 97.92,20.29 97.76,20.14 95.4,20.14 94.79,19.53 93.4,19.53 92.53,18.67 92.53,13.26 91.26,11.99 91.26,4.52 90.92,4.18 76.54,4.18 76.09,4.64 76.09,27.95 76.4,28.27 83.54,28.27 88.06,23.75
VRECT on TOP: 41.77,18.69 42.88,18.69 44.8,16.76 45.6,16.76 46.24,16.13 46.24,14.37 45.53,13.66 41.94,13.66 41.44,14.16 41.44,18.36
VRECT on BOTTOM: 68.92,46.76 68.92,47.49 68.23,48.18 67.65,48.18 67.37,48.46 67.37,48.81 67.65,49.09 69.55,49.09 70.34,48.31 70.34,46.71 70.09,46.45 69.22,46.45
N11474046 on BOTTOM: 5.84,13.47 1.91,13.47 0.91,12.48 0.91,5.82 1.5,5.23 3.71,5.23 4.5,6.02 4.5,9.43 6.5,11.44 6.5,12.81
N11474062 on BOTTOM (solid shape): 30.61,22.38 30.61,20.26 29.87,19.52 28.4,19.52 27.61,20.31 27.61,21.88 27.61,21.88 27.61,22.38 28.11,22.88 28.61,22.38 29.11,22.88 29.61,22.38 30.11,22.88
N11474062 on BOTTOM: 16.28,4.25 18.67,6.64 25.12,6.64 28.6,10.12 28.6,18.02 30.61,20.02 30.61,20.84 29.84,21.6 28.22,21.6 26.11,19.49 26.11,12.13 23.8,9.81 17.32,9.81 15.95,8.44 7.92,8.44 7.04,7.55 7.04,4.95 7.74,4.25
N11474114 on BOTTOM (solid shape): 30.61,26.15 30.61,24.08 30.11,23.58 29.61,24.08 29.11,23.58 28.61,24.08 28.11,23.58 27.61,24.08 27.61,26.1 28.4,26.89 29.87,26.89
N11474114 on BOTTOM: 30.43,24.72 28.09,24.72 27.36,25.46 27.36,26.6 24.09,29.87 21.52,29.87 17.75,33.63 17.75,41.02 13.77,45.01 13.77,54.2 14.35,54.79 15.49,54.79 16.03,54.25 16.03,46.05 20.24,41.83 20.24,35.99 23.51,32.72 25.53,32.72 30.94,27.31 30.94,25.23
N11474138 on BOTTOM: 10.57,45.01 11.68,45.01 12.24,45.57 12.24,54.28 11.71,54.81 10.49,54.81 9.88,54.2 9.88,45.69
N11474236 on BOTTOM (solid shape): 22.99,22.38 22.99,20.26 22.25,19.52 20.78,19.52 19.99,20.31 19.99,21.88 19.99,21.88 19.99,22.38 20.49,22.88 20.99,22.38 21.49,22.88 21.99,22.38 22.49,22.88
N11474236 on BOTTOM: 3.86,23.68 3.86,21.14 4.34,20.66 11.2,20.66 11.89,19.97 11.89,15.45 14.05,13.29 22.53,13.29 23.01,13.78 23.01,20.46 22.76,20.71 19.99,20.71 19.99,17.36 19.08,16.44 16.38,16.44 15.11,17.71 15.11,22.62 13.89,23.83 4.01,23.83
N11474420 on BOTTOM (solid shape): 22.99,26.15 22.99,24.08 22.49,23.58 21.99,24.08 21.49,23.58 20.99,24.08 20.49,23.58 19.99,24.08 19.99,26.1 20.78,26.89 22.25,26.89
N11474420 on BOTTOM: 22.63,24.37 16.94,24.37 12.98,28.33 5.66,28.33 2.34,31.66 2.34,37.22 4.09,38.97 11.86,38.97 12.52,38.31 12.52,36.03 11.73,35.24 6.12,35.24 5.59,34.71 5.59,33.46 7.49,31.56 14.81,31.56 18.95,27.42 22.05,27.42 23.01,26.45 23.01,24.75
N11475153 on TOP: 37.91,49.43 38.35,48.99 38.35,48.99 38.57,48.77 44.04,48.77 45.76,50.48 45.76,53.02 45.06,53.72 38.89,53.72 37.91,52.74
N11475153 on TOP: 94.68,35.61 87.84,35.61 80.91,42.54 80.91,44 80.34,44.57 77.43,44.57 77.15,44.29 77.15,42.95 77.17,42.93 77.17,40.34 83.8,33.7 94.5,33.7 95.06,34.26 95.06,35.23
N11475153 on BOTTOM: 79.23,42.85 78.98,42.59 77.05,42.59 76.84,42.8 76.84,50.14 72.55,54.43 72.54,54.43 71.73,55.24 48.34,55.24 45.77,52.68 45.77,50.5 44.04,48.77 38.57,48.77 37.91,49.43 37.91,52.77 38.86,53.72 43.94,53.72 47.35,57.12 47.35,59.92 48.08,60.66 75.38,60.66 79.23,56.8
N11475153 on BOTTOM: 94.55,35.61 91.04,35.61 90.81,35.38 90.81,32.44 91.03,32.22 92.46,32.22 92.72,32.48 92.72,33.17 93.28,33.73 94.57,33.73 95.03,34.18 95.03,35.12
N11475153 on BOTTOM: 68.11,34.11 68.01,34.21 68.01,35.43 68.58,36 71.29,36 71.54,35.76 71.54,35.23 70.42,34.11
N11476179 on BOTTOM (solid shape): 49.59,35.56 45.79,35.56 45.79,37.81 43.99,37.81 43.99,40.51 45.64,40.51 45.64,42.46 45.74,42.46 46.66,42.84 47.04,43.76 47.04,43.86 49.59,43.86
N11476179 on TOP: 44.05,42.39 43.65,41.98 43.65,31.09 43.65,31.08 43.65,25.86 43.66,25.85 43.66,23.35 43.66,23.34 43.66,22.68 46.33,20.02 52.43,20.02 55.83,23.42 55.83,48.44 54.86,49.4 48.44,49.4 47.12,48.08 47.12,43.26 46.25,42.39
N11476179 on BOTTOM: 47.05,43.2 45.65,41.8 45.65,40.48 44.51,40.48 44.26,40.23 44.26,38.1 44.54,37.82 45.86,37.82 45.86,35.25 43.65,33.04 43.65,22.7 47.67,18.67 47.67,13.75 43.65,9.73 43.65,2.63 44.15,2.13 58.04,2.13 58.94,3.03 58.94,25.62 53.59,30.98 53.59,43.44 54.48,44.34 54.48,52.96 53.31,54.13 49.83,54.13 49.05,53.34 49.05,51.36 47.05,49.36
N11479125 on BOTTOM: 58.4,43.81 58.4,47.49 58.27,47.62 57.3,47.62 57.14,47.47 57.14,44.46 56.7,44.01 56.7,43.73 56.78,43.66 58.25,43.66
N11479237 on BOTTOM: 57.41,43.25 58.68,43.25 59.06,43.63 59.06,45.87 59.27,46.07 60.28,46.07 60.89,46.68 60.89,47.24 64.83,51.18 72.37,51.18 74.51,49.04 74.51,32.72 73.08,31.29 73.08,19.76 72.01,18.69 63.73,18.69 62.95,19.47 62.95,26.77 61.17,28.55 61.17,31.03 61.27,31.14 64.53,31.14 65.39,30.27 69.73,30.27 70.21,30.76 70.21,33.19 71.97,34.95 71.97,35.91 71.56,36.32 64.58,36.32 64.47,36.42 64.47,39.8 64.55,39.87 69.4,39.87 71.07,41.54 71.07,48.27 69.91,49.42 67.45,49.42 66.3,48.28 63.81,48.28 63.2,47.67 63.2,43.91 63.1,43.81 61.88,43.81 60.99,42.92 57.41,42.92 57.36,42.97 57.36,43.2
N11479555 on BOTTOM: 57.29,40.66 58.71,40.66 60.16,39.21 60.16,38.65 60.28,38.53 63.64,38.53 63.71,38.6 63.71,39.77 63.64,39.85 60,39.85 58.86,40.99 57.29,40.99 57.21,40.92 57.21,40.74
N11479611 on BOTTOM: 60.59,37.56 63.23,37.56 63.48,37.31 63.48,36.6 63.38,36.5 60.59,36.5 60.41,36.67 60.41,37.38
N11480020 on BOTTOM: 57.24,41.75 61.1,41.75 61.58,41.27 63.2,41.27 64.02,42.08 64.02,43.89 64.3,44.17 65.03,44.17 65.36,43.84 65.36,40.99 64.63,40.26 60.03,40.26 58.89,41.4 57.24,41.4 57.18,41.45 57.18,41.7
N11480864 on BOTTOM: 66.79,44.22 70.01,44.22 70.27,43.96 70.27,43.05 70.06,42.85 66.76,42.85 66.58,43.02 66.58,44.01
N11480868 on BOTTOM: 64.63,47.57 67.47,47.57 67.73,47.32 67.73,46.3 67.57,46.15 64.53,46.15 64.35,46.33 64.35,47.29
N11482311 on BOTTOM: 66,32.18 69.1,32.18 69.3,31.97 69.3,31.06 69.05,30.81 65.87,30.81 65.69,30.98 65.69,31.87
N11482333 on BOTTOM: 62.62,35.45 66.51,35.45 66.84,35.12 66.84,34.34 66.63,34.13 62.62,34.13 62.47,34.29 62.47,35.3
N11482355 on BOTTOM: 57.03,39.9 58.53,39.9 58.94,39.49 58.94,29.89 59.06,29.76 60.33,29.76 60.49,29.92 60.49,35.56 59.85,36.19 59.85,39.06 58.66,40.26 57.03,40.26 56.96,40.18 56.96,39.98
N11498787 on TOP: 138.51,33.3 140.63,35.42 140.63,39.78 138.18,42.23 138.18,48.06 138.76,48.64 140.69,48.64 141.5,47.83 141.5,43.23 144.22,40.51 144.22,33.88 139.18,28.84 131.99,28.84 130.28,27.13 128.09,27.13 128.09,29.59 131.8,33.3
N11498787 on BOTTOM: 118.47,27.91 119.68,29.12 127.66,29.12 131.8,33.25 138.46,33.25 140.67,35.46 140.67,39.73 138.18,42.21 138.18,48.03 138.79,48.64 140.69,48.64 141.5,47.83 141.5,43.23 144.2,40.54 144.2,33.86 139.19,28.85 131.84,28.85 126.65,23.67 119.62,23.67 119.44,23.85 119.44,24.42 119.69,24.67 126.21,24.67 127.62,26.08 127.62,26.23 127.56,26.29 127.39,26.29 126.26,25.16 118.98,25.16 118.47,25.66
N11498945 on BOTTOM: 89.29,32.53 89.29,35.4 89.14,35.56 89.11,35.56 88.96,35.71 85.94,35.71 85.33,35.1 85.33,34.06 85.96,33.42 86.8,33.42 87.99,32.23 88.99,32.23
N11499171 on TOP: 127.22,59.24 126.72,59.74 111.71,59.74 111.1,59.13 111.1,44.32 114.55,40.87 122.66,40.87 125.82,37.71 126.97,37.71 127.22,37.95
N11499171 on BOTTOM: 118.2,34.51 118.2,36.75 116.65,38.3 114.17,38.3 113.13,39.34 113.13,54.38 114.43,55.68 122.1,55.68 122.43,55.35 122.43,53.16 122.83,52.76 125.17,52.76 125.72,52.21 125.72,49.9 127.08,48.54 127.08,37.82 122.9,33.64 119.07,33.64
N11499175 on BOTTOM: 123.8,54.86 123.8,53.62 123.93,53.49 127.94,53.49 128.07,53.62 128.07,54.79 127.89,54.97 123.9,54.97
N11499225 on BOTTOM: 95.34,26.89 94.6,26.16 93.71,26.16 92.34,27.53 92.34,30.65 92.54,30.86 93.58,30.86 93.94,30.5 93.94,28.37 94.4,27.91 97.87,27.91 97.95,27.83 97.95,26.97 97.88,26.89
N11499609 on BOTTOM: 109.79,22.4 110.98,22.4 111.27,22.11 111.27,18.07 110.51,17.3 110.51,16.13 110.67,15.97 113.99,15.97 114.17,16.15 114.17,19.77 111.16,22.78 109.79,22.78 109.74,22.73 109.74,22.45
N11499655 on BOTTOM: 109.74,25.02 111.97,25.02 112.53,25.57 113.73,25.57 113.88,25.42 113.88,24.33 113.7,24.15 112.51,24.15 112,24.66 109.71,24.66 109.64,24.74 109.64,24.91
N11939314 on BOTTOM: 61.5,33.09 64.04,33.09 64.32,32.81 64.32,32.33 64.02,32.03 61.55,32.03 61.38,32.2 61.38,32.97
N11995900 on BOTTOM: 60.41,46.76 60.49,46.83 60.49,48 62.67,50.19 62.67,51.66 62.44,51.89 59.55,51.89 59.47,51.81 59.47,50.75 59.56,50.66 59.79,50.66 59.98,50.47 59.98,48.71 59.6,48.33 59.6,46.76
N12000412 on BOTTOM: 66.25,41.86 69.12,41.86 69.28,41.7 69.28,40.84 69.12,40.69 66.28,40.69 66.15,40.81 66.15,41.75
N12033400 on BOTTOM: 129.83,22.4 130.16,22.74 134.5,22.74 134.5,22.73 135.72,22.73 135.8,22.81 135.8,23.87 135.24,24.43 130.81,24.43 128.91,22.53 128.91,20.34 128.05,19.48 125.18,19.48 124.19,18.49 123.73,18.49 123.58,18.33 123.58,17.5 124.52,16.56 124.52,15.67 124.72,15.46 125.41,15.46 125.61,15.67 125.61,16.43 125.05,16.99 125.05,17.88 125.43,18.26 129.22,18.26 129.83,18.87
N12033400 on BOTTOM: 146.84,35 146.84,28.96 146.66,28.78 145.77,28.78 145.59,28.96 145.59,34.7 145.9,35
N12033444 on BOTTOM: 147.9,34.95 147.9,33.53 148.13,33.3 150.67,33.3 150.88,33.5 150.88,34.75 150.6,35.03 147.98,35.03
N12033508 on BOTTOM: 148.13,31.29 148.13,32.18 148.29,32.33 150.8,32.33 153.37,29.77 153.37,27.84 153.06,27.53 152.27,27.53 152.07,27.74 152.07,29.67 150.57,31.17 148.26,31.17
N12033698 on BOTTOM: 139.46,17.09 139.46,19.73 139.86,20.14 141.31,20.14 141.31,20.75 139.58,20.75 138.34,19.5 138.34,17.12 138.57,16.89 139.25,16.89
N12033710 on BOTTOM: 144.87,14.52 143.98,14.52 143.8,14.7 143.8,15.41 142.5,16.71 142.5,18.51 142.15,18.87 142.15,20.21 142.22,20.29 143.27,20.29 145.42,22.45 147.99,22.45 148.09,22.35 148.09,20.93 147.89,20.72 144.94,20.72 143.98,19.76 143.98,17.09 145.12,15.95 145.12,14.78
N12033758 on BOTTOM: 137.37,28.19 139.58,28.19 139.81,27.96 139.81,27.25 139.66,27.1 137.37,27.1 137.27,27.2 137.27,28.09
N12033766 on BOTTOM: 141.31,22.68 139.84,22.68 138.67,23.85 138.67,26.18 139.99,26.18 140.78,26.97 142.43,26.97 142.43,25.4 141.31,24.28
N12033774 on BOTTOM: 139.86,22.02 141.67,22.02 142.12,22.48 142.12,24.51 142.2,24.58 143.42,24.58 143.52,24.48 143.52,21.28 143.39,21.15 141.56,21.15 141.31,21.41 139.86,21.41
N12033856 on BOTTOM: 135.94,24.92 136.53,24.33 137.84,24.33 137.95,24.43 137.95,25.53 136.93,26.54 132.66,26.54 132.49,26.37 132.49,25.2 132.76,24.92
N12033856 on BOTTOM: 146.8,19.94 146.8,17.24 146.64,17.09 145.73,17.09 144.28,18.54 144.28,19.53 144.76,20.01 146.72,20.01
N12033928 on BOTTOM: 144.38,23.57 144.38,26.46 144.64,26.72 145.12,26.72 145.5,26.34 145.5,23.59 145.3,23.39 144.56,23.39
N12034132 on BOTTOM: 135.85,20.75 130.59,20.75 130.4,20.56 130.4,17.43 130.39,17.42 131.09,16.71 132.59,16.71 133.07,17.2 133.07,18.41 133.6,18.95 133.6,19.91 133.83,20.14 135.85,20.14
N12034136 on BOTTOM: 137.32,17.12 137.32,20.95 136.25,22.02 134.4,22.02 134.14,22.28 130.57,22.28 130.39,22.1 130.39,21.2 130.56,21.03 133.51,21.03 133.88,21.41 135.95,21.41 136.18,21.18 136.18,17.09 136.41,16.86 137.07,16.86
N12052159 on BOTTOM: 116.54,16.05 117.71,16.05 118.78,17.12 120.28,17.12 121.04,16.35 122.18,16.35 123.05,15.49 123.81,15.49 123.89,15.57 123.89,16.38 123.53,16.73 123.15,16.73 121.7,18.18 117.54,18.18 116.42,17.06 116.42,16.18
N12053445 on BOTTOM: 89.16,30.93 87.61,30.93 86.5,32.05 85.38,32.05 85.12,31.8 85.12,30.86 87.08,28.9 89.37,28.9 89.9,29.43 89.9,30.2
N12080403 on BOTTOM: 128.41,17.29 128.51,17.4 129.63,17.4 130.96,16.06 130.96,15.98 130.89,15.9 128.57,15.9 128.41,16.07
N12174734 on BOTTOM: 118.9,7.65 120.29,7.65 121.36,8.71 121.36,9.8 121.49,9.93 122.45,9.93 122.56,9.83 122.56,8.56 120.5,6.5 119.02,6.5 118.87,6.65 118.87,7.62
N12288102 on TOP: 142.77,49.73 142.77,43.99 146,40.77 152.6,40.77 153.26,41.43 153.26,49.71 152.65,50.32 143.36,50.32
N12288102 on BOTTOM: 142.75,49.73 142.75,43.99 145.97,40.77 152.58,40.77 153.24,41.43 153.24,49.71 152.63,50.32 143.33,50.32
N12288115 on TOP: 141.66,60.27 141.66,52.98 142.39,52.25 152.7,52.25 153.24,52.78 153.24,60.35 152.88,60.71 142.09,60.71
N12288115 on BOTTOM: 141.68,60.27 141.68,52.98 142.42,52.25 152.73,52.25 153.26,52.78 153.26,60.35 152.91,60.71 142.11,60.71

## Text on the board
Ref Des/Silkscreen Bottom: TM | HiperPFS -4 | A | LYTSwitch -6 | *
Ref Des/Silkscreen Top: L | N | 1947 | S/N | DER 901 Rev A | VOUT | DIM+ | RTN | DIM-
User.6: SLOTS | DELETE THESE HOLES: | 1.  THROUGH HOLES ARE PLATED THROUGH. | EXCEPTIONS WILL BE NOTED IN DRILL CHART "NOTE". | 2.  MATERIAL: BASE MATERIAL LAMINATED EPOXY | UL APPROVED MANUFACTURED SOURCE FOR FR4. | 3.  SOLDER PLATE WILL BE RoHS COMPLIANT. | 4.  SOLDER MASK LPI (LIQUID PHOTO IMAGEABLE) BOTH SIDES. COLOR GREEN. | SOLDER MASK (REGISTRATION) -0/+0.003" | 5.  SILKSCREEN TOP/BOTTOM SIDE. COLOR WHITE. (MIN.WIDTH 0.005" MAX.WIDTH 0.010") | 6.  FINISH TO BE SMOBC. | 7.  ENIG OR RoHS COMPLIANT. | 8.  BOARD DIMENSION +/- 0.005" | 9.  DRILL TOLERANCE +/- 0.003" | 10. TRACE WIDTH UNDER 0.010" +/- 0.002" | TRACE WIDTH OVER 0.011" +/- 0.005" | 11. TRACE SPACE +/- 0.003" | 12. MATERIAL FR4 COPPER 2 OZ BOARD THICKNESS 0.062" | NOTES: UNLESS OTHERWISE SPECIFIED
User.9: FIGURE | FINISHED_SIZE | 12.0 | 20.0 | 30.0 | 38.0 | 40.0 | 46.0 | 50.0 | 52.0 | 55.0 | 60.0 | DRILL CHART: TOP to BOTTOM | ALL UNITS ARE IN MILS | PLATED | QTY | 534 | 22 | 8 | 2 | 20 | 12 | 4 | 30 | 3
